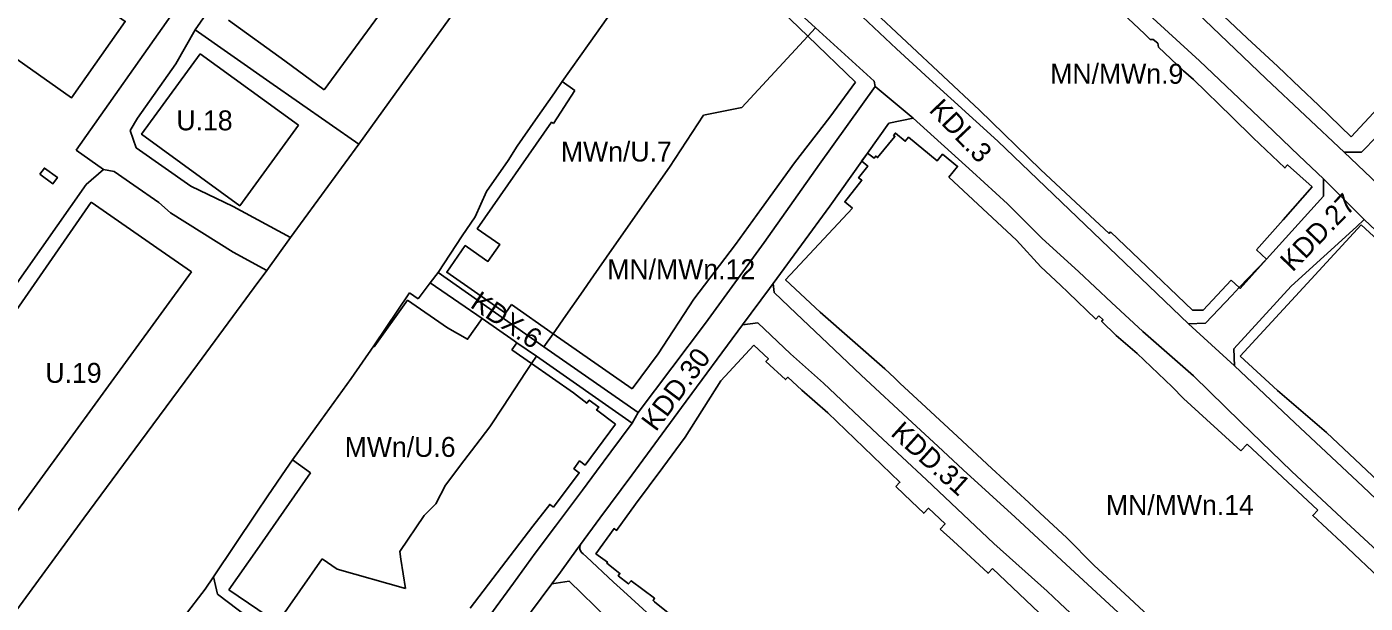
# Model space of a CAD drawing. Extents: x 7425067 to 7426806, y 5549054 to 5550619.
# Drawn here: x 7426205.4 to 7426541.6, y 5549482.5 to 5549627.2 of the extents above; entities that cross this region are included whole.
import ezdxf

# ---------------------------------------------------------------- set-up
doc = ezdxf.new("R2010")
doc.units = 0
for name, color, linetype in [('LIN_Linia Zabudowy Nieprzekraczalna', 7, 'Continuous'), ('LIN_linia zabudowy obowiązująca', 7, 'Continuous'), ('LIN_linie_rozgraniczajace', 7, 'Continuous'), ('TXT_Oznaczenia_przeznaczen', 7, 'Continuous')]:
    doc.layers.add(name, color=color, linetype=linetype)

msp = doc.modelspace()

# ---------------------------------------------------------------- linework, layer by layer
at = {"layer": 'LIN_Linia Zabudowy Nieprzekraczalna'}
for points in [[(7426538.0268, 5549599.6257), (7426544.74, 5549606.81), (7426559.36, 5549622.35), (7426563.29, 5549626.51), (7426564.58, 5549625.28), (7426566.52, 5549627.33), (7426565.24, 5549628.54), (7426567.25, 5549630.67), (7426561.59, 5549636.03), (7426548.12, 5549648.56), (7426531.28, 5549664.88), (7426518.913, 5549676.7566), (7426478.07, 5549715.98), (7426464.99, 5549727.97), (7426453.6444, 5549738.2083), (7426440.2683, 5549750.2788)], [(7426442.66, 5549689.14), (7426443.3845, 5549689.9043), (7426445.3474, 5549688.063), (7426453.04, 5549680.77), (7426454.4822, 5549679.4051), (7426458.9674, 5549675.0954), (7426463.0302, 5549671.2622), (7426469.4399, 5549665.1439), (7426475.3736, 5549659.3903), (7426481.0322, 5549653.9703), (7426484.8352, 5549650.3881), (7426488.7822, 5549646.5623), (7426492.7561, 5549642.6881), (7426498.8215, 5549636.8419), (7426511.9317, 5549624.3494), (7426519.6144, 5549617.2769), (7426525.2257, 5549611.917), (7426529.8193, 5549607.5641), (7426538.0268, 5549599.6257)], [(7426487.6123, 5549624.0024), (7426486.1182, 5549625.4194), (7426475.0591, 5549635.938), (7426467.2851, 5549643.3718), (7426463.1098, 5549647.3578), (7426452.6961, 5549657.1819), (7426444.552, 5549664.9118), (7426440.8931, 5549668.0124), (7426429.2534, 5549678.9537), (7426426.5198, 5549681.588)], [(7426378.39, 5549669.82), (7426383.61, 5549664.48), (7426386.01, 5549661.89), (7426400.55, 5549647.58), (7426399.82, 5549646.84), (7426408.17, 5549638.76), (7426409.02, 5549639.64), (7426417.3229, 5549631.8468), (7426444.72, 5549606.26), (7426460.04, 5549591.38), (7426467.6303, 5549584.2897), (7426477.25, 5549575.34), (7426477.5977, 5549575.714)], [(7426413.6, 5549613.31), (7426401.6206, 5549624.8545), (7426380, 5549645.69), (7426370.03, 5549652.54)], [(7426357.542, 5549634.3437), (7426355.61, 5549635.73), (7426346.69, 5549623.04), (7426339.9401, 5549613.4599)], [(7426256.0787, 5549628.8601), (7426270.22, 5549618.64), (7426280.1535, 5549611.3656)], [(7426489.6382, 5549622.0813), (7426489.47, 5549623.1), (7426488.36, 5549624.01), (7426487.6123, 5549624.0024)], [(7426528.27, 5549587.03), (7426522.08, 5549592.52), (7426521.4267, 5549591.7827), (7426513.4053, 5549599.3408), (7426508.0428, 5549604.5824), (7426498.4858, 5549613.9524), (7426495.9139, 5549616.1301), (7426489.6382, 5549622.0813)], [(7426339.9401, 5549613.4599), (7426343.1003, 5549611.2344)], [(7426398.29, 5549593.06), (7426407.14, 5549604.52), (7426413.6, 5549613.31)], [(7426343.1003, 5549611.2344), (7426337.727, 5549602.9229)], [(7426337.727, 5549602.9229), (7426337.26, 5549603.25), (7426318.57, 5549576.53), (7426324.24, 5549572.58), (7426321.26, 5549568.32), (7426316.12, 5549571.9), (7426315.55, 5549572.3), (7426310.91, 5549565.61), (7426325.65, 5549555.29), (7426327.1969, 5549557.4998)], [(7426437.001, 5549589.4907), (7426439.19, 5549592.16), (7426435.44, 5549595.23), (7426434.1, 5549593.59), (7426426.91, 5549599.48), (7426426.08, 5549598.48), (7426423.59, 5549600.53), (7426423.12, 5549599.95), (7426423.45, 5549599.68), (7426419.1, 5549594.37), (7426418.64, 5549594.74), (7426418.24, 5549594.21), (7426416.62, 5549595.5), (7426416.4114, 5549595.2369), (7426415.05, 5549593.52), (7426415.1399, 5549593.4485), (7426416.66, 5549592.24), (7426414.35, 5549589.33), (7426415.19, 5549588.67), (7426410.86, 5549583.24), (7426412.8563, 5549581.6544)], [(7426208.7375, 5549590.1894), (7426212.01, 5549587.83), (7426213.14, 5549589.4), (7426209.8667, 5549591.7583), (7426208.7375, 5549590.1894)], [(7426357.4565, 5549536.3315), (7426363.97, 5549545.12), (7426373, 5549558.85), (7426383.43, 5549572.57), (7426389.96, 5549581.63), (7426398.29, 5549593.06)], [(7426454, 5549573.65), (7426437.001, 5549589.4907)], [(7426514.2675, 5549571.2269), (7426520.96, 5549578.78), (7426528.27, 5549587.03)], [(7426412.8563, 5549581.6544), (7426396.03, 5549563.69), (7426404.67, 5549555.61), (7426420.91, 5549541.33), (7426423.35, 5549539.08), (7426424.73, 5549537.74), (7426431.3126, 5549531.6576), (7426439.18, 5549524.38), (7426447.81, 5549516.35), (7426457.06, 5549507.81), (7426459.86, 5549505.23), (7426466.65, 5549498.95), (7426473.46, 5549492.05), (7426482.4, 5549483.78), (7426487.2, 5549479.22), (7426492.88, 5549473.96), (7426510.35, 5549457.84), (7426515.95, 5549452.58), (7426520.98, 5549447.85), (7426523.82, 5549444.93), (7426531.3, 5549437.91), (7426537.37, 5549444.38), (7426550.43, 5549458.71), (7426562.87, 5549471.53)], [(7426477.5977, 5549575.714), (7426484.88, 5549568.76), (7426498.19, 5549556.05)], [(7426540.53, 5549577.51), (7426528.01, 5549563.88), (7426510.21, 5549544.55)], [(7426606.1385, 5549514.944), (7426600.47, 5549519.88), (7426593.35, 5549526.08), (7426546.9922, 5549567.8692), (7426548.84, 5549569.88), (7426540.53, 5549577.51)], [(7426460.12, 5549566.97), (7426454, 5549573.65)], [(7426507.94, 5549563.63), (7426509.953, 5549561.7343), (7426510.17, 5549561.53), (7426516.77, 5549568.9), (7426514.2675, 5549571.2269)], [(7426474.72, 5549554.68), (7426473.9139, 5549553.8538), (7426466.99, 5549560.48), (7426465.09, 5549562.35), (7426460.12, 5549566.97)], [(7426498.19, 5549556.05), (7426500.88, 5549556.1), (7426507.94, 5549563.63)], [(7426311.08, 5549551.63), (7426301.07, 5549558.56), (7426292.89, 5549547.1), (7426292.8, 5549546.9501), (7426292.57, 5549547.11), (7426286.93, 5549538.92), (7426279.32, 5549528.36), (7426272.2108, 5549518.4955)], [(7426327.1969, 5549557.4998), (7426337.6156, 5549550.1757), (7426357.4565, 5549536.3315)], [(7426319.7682, 5549553.9465), (7426316.13, 5549548.79), (7426311.08, 5549551.63)], [(7426327.2291, 5549546.1391), (7426328.5027, 5549547.9161), (7426327.86, 5549548.36), (7426319.7682, 5549553.9465)], [(7426493.06, 5549536.85), (7426484.31, 5549545.18), (7426479.07, 5549549.7), (7426475.36, 5549553.3), (7426475.74, 5549553.69), (7426474.72, 5549554.68)], [(7426353.3, 5549527.48), (7426348.53, 5549531.02), (7426349.07, 5549531.74), (7426346.69, 5549533.51), (7426346.09, 5549532.71), (7426342.71, 5549535.35), (7426332.2044, 5549542.6717), (7426327.2291, 5549546.1391)], [(7426388.01, 5549547.25), (7426379.73, 5549538.35), (7426370.82, 5549524.17), (7426365.2, 5549516.56), (7426358.3, 5549507.38), (7426353.55, 5549500.8), (7426352.92, 5549501.26), (7426348.36, 5549494.93), (7426351.28, 5549492.83), (7426351.09, 5549492.57), (7426354.41, 5549490), (7426353.97, 5549489.41), (7426356.55, 5549487.37), (7426357.22, 5549488.15), (7426363.12, 5549483.75), (7426362.74, 5549483.17), (7426363.13, 5549482.88), (7426378.18, 5549470.72), (7426382.81, 5549466.07), (7426382.87, 5549466.2), (7426388.4, 5549460.7), (7426394.14, 5549454.53), (7426399.56, 5549448.92), (7426403.0973, 5549445.2587)], [(7426406.59, 5549530.28), (7426400.09, 5549536.03), (7426396.58, 5549539.25), (7426396.03, 5549538.65), (7426391.08, 5549543.19), (7426391.7, 5549543.87), (7426388.01, 5549547.25)], [(7426510.21, 5549544.55), (7426519.55, 5549535.9), (7426531.82, 5549525.34), (7426540.51, 5549517.25), (7426563.54, 5549495.57), (7426577.1, 5549483.08), (7426582.613, 5549489.0782), (7426585.65, 5549486.27), (7426593.11, 5549494.36)], [(7426510.3065, 5549520.7445), (7426495.91, 5549533.91), (7426493.06, 5549536.85)], [(7426423.6718, 5549511.7983), (7426424.71, 5549512.88), (7426406.59, 5549530.28)], [(7426337.76, 5549506.6), (7426344.2, 5549515.26), (7426342.84, 5549516.27), (7426344.2897, 5549518.2197), (7426345.67, 5549517.19), (7426353.3, 5549527.48)], [(7426511.9, 5549522.46), (7426510.3065, 5549520.7445)], [(7426529.67, 5549505.9), (7426511.9, 5549522.46)], [(7426272.2108, 5549518.4955), (7426276.7026, 5549515.2122)], [(7426276.7026, 5549515.2122), (7426263.27, 5549496.01), (7426256.1733, 5549485.865)], [(7426434.84, 5549501.14), (7426436.08, 5549502.46), (7426431.9, 5549506.33), (7426430.71, 5549505.08), (7426427.63, 5549508.02), (7426423.6718, 5549511.7983)], [(7426316.82, 5549481.26), (7426332.57, 5549501.84), (7426336.7731, 5549507.332), (7426337.76, 5549506.6)], [(7426546.56, 5549487.47), (7426535.59, 5549497.8), (7426528.39, 5549504.53), (7426529.67, 5549505.9)], [(7426448, 5549491.22), (7426446.88, 5549490.04), (7426438.1, 5549498.14), (7426434.84, 5549501.14)], [(7426463.77, 5549477.75), (7426463.02, 5549476.94), (7426454.68, 5549484.87), (7426448, 5549491.22)], [(7426256.1733, 5549485.865), (7426268.433, 5549477.5449), (7426274.57, 5549473.38), (7426283.19, 5549467.53), (7426283.6963, 5549468.2744)]]:
    msp.add_lwpolyline(points, dxfattribs=at)
at = {"layer": 'LIN_linia zabudowy obowiązująca'}
for points in [[(7426203.81, 5549647.1), (7426184.83, 5549631.79), (7426216.68, 5549609.4), (7426230.16, 5549628.58), (7426203.81, 5549647.1)], [(7426280.1535, 5549611.3656), (7426296.7731, 5549634.1389)], [(7426249.01, 5549620.45), (7426234.27, 5549600.25), (7426258.92, 5549582.27), (7426273.7219, 5549602.5527)], [(7426273.7219, 5549602.5527), (7426249.01, 5549620.45)], [(7426221.62, 5549583.21), (7426169.3369, 5549507.8784)], [(7426246.8404, 5549565.7177), (7426239.21, 5549571.01), (7426221.62, 5549583.21)], [(7426192.6914, 5549491.5189), (7426246.8404, 5549565.7177)]]:
    msp.add_lwpolyline(points, dxfattribs=at)
at = {"layer": 'LIN_linie_rozgraniczajace'}
for points in [[(7426472.2007, 5549656.8053), (7426516.68, 5549614.14)], [(7426323.635, 5549645.995), (7426300.92, 5549614.51)], [(7426247.76, 5549626.42), (7426254.995, 5549637.01)], [(7426346.69, 5549623.04), (7426355.61, 5549635.73)], [(7426397, 5549632.91), (7426403.56, 5549626.95)], [(7426499.92, 5549618.67), (7426483.42, 5549633.83)], [(7426242, 5549630.59), (7426217.83, 5549596.2)], [(7426415.31, 5549629.69), (7426423.85, 5549621.67)], [(7426247.76, 5549626.42), (7426242.85, 5549617.9)], [(7426247.76, 5549626.42), (7426266.52, 5549613.31)], [(7426385.05, 5549606.95), (7426401.6206, 5549624.8545), (7426403.56, 5549626.95)], [(7426403.56, 5549626.95), (7426418.2677, 5549613.5875)], [(7426339.9401, 5549613.4599), (7426346.69, 5549623.04)], [(7426423.85, 5549621.67), (7426432.04, 5549614.18)], [(7426516.62, 5549602.85), (7426499.92, 5549618.67)], [(7426233.29, 5549604.29), (7426242.85, 5549617.9)], [(7426266.52, 5549613.31), (7426288.82, 5549597.74)], [(7426300.92, 5549614.51), (7426288.82, 5549597.74)], [(7426337.94, 5549610.62), (7426339.9401, 5549613.4599)], [(7426418.52, 5549612.2), (7426404.52, 5549592.73)], [(7426418.2677, 5549613.5875), (7426418.52, 5549612.2)], [(7426418.52, 5549612.2), (7426428.02, 5549604.31)], [(7426432.04, 5549614.18), (7426449.33, 5549598.49)], [(7426516.68, 5549614.14), (7426536.2854, 5549595.7734)], [(7426333.235, 5549603.855), (7426337.94, 5549610.62)], [(7426540.67, 5549595.7725), (7426556.37, 5549611.79)], [(7426375.36, 5549605.03), (7426385.05, 5549606.95)], [(7426231.38, 5549601.16), (7426233.29, 5549604.29)], [(7426328.6285, 5549597.2471), (7426333.235, 5549603.855)], [(7426366.8182, 5549591.9749), (7426375.36, 5549605.03)], [(7426416.57, 5549595.46), (7426421.96, 5549603.04)], [(7426421.96, 5549603.04), (7426428.02, 5549604.31)], [(7426428.02, 5549604.31), (7426442.92, 5549590.78)], [(7426524.92, 5549594.94), (7426516.62, 5549602.85)], [(7426231.38, 5549601.16), (7426232.94, 5549596.84)], [(7426449.33, 5549598.49), (7426497.2024, 5549552.684)], [(7426217.83, 5549596.2), (7426224.69, 5549591.38)], [(7426232.94, 5549596.84), (7426246.62, 5549587.22)], [(7426288.82, 5549597.74), (7426271.7, 5549574.3)], [(7426326.38, 5549593.66), (7426328.6285, 5549597.2471)], [(7426407.15, 5549582.21), (7426415.1399, 5549593.4485), (7426416.4114, 5549595.2369), (7426416.57, 5549595.46)], [(7426548.1702, 5549584.4192), (7426536.2854, 5549595.7734)], [(7426536.2854, 5549595.7734), (7426540.67, 5549595.7725)], [(7426320.92, 5549585.84), (7426326.38, 5549593.66)], [(7426352.41, 5549571.27), (7426366.8182, 5549591.9749)], [(7426404.52, 5549592.73), (7426390.61, 5549573.06)], [(7426531.1317, 5549589.012), (7426524.92, 5549594.94)], [(7426224.69, 5549591.38), (7426220.38, 5549587.66)], [(7426227.35, 5549590.86), (7426224.69, 5549591.38)], [(7426232.35, 5549587.45), (7426227.35, 5549590.86)], [(7426442.92, 5549590.78), (7426451.7, 5549582.74)], [(7426531.1317, 5549589.012), (7426541.33, 5549578.84)], [(7426531.1385, 5549584.6905), (7426531.1317, 5549589.012)], [(7426220.38, 5549587.66), (7426163.57, 5549506.84)], [(7426238.61, 5549583.09), (7426232.35, 5549587.45)], [(7426246.62, 5549587.22), (7426257.29, 5549582.08)], [(7426318.05, 5549579.51), (7426320.92, 5549585.84)], [(7426241.54, 5549580.52), (7426238.61, 5549583.09)], [(7426257.29, 5549582.08), (7426271.7, 5549574.3)], [(7426392.9036, 5549562.76), (7426407.15, 5549582.21)], [(7426451.7, 5549582.74), (7426460.38, 5549574.11)], [(7426516.77, 5549568.9), (7426531.1385, 5549584.6905)], [(7426257.28, 5549570.63), (7426241.54, 5549580.52)], [(7426314.76, 5549574.73), (7426318.05, 5549579.51)], [(7426539.3546, 5549577.0327), (7426541.33, 5549578.84)], [(7426557.16, 5549563.9), (7426541.33, 5549578.84)], [(7426523, 5549562.07), (7426539.3546, 5549577.0327)], [(7426271.7, 5549574.3), (7426265.72, 5549566.07)], [(7426308.79, 5549565.55), (7426314.76, 5549574.73)], [(7426390.61, 5549573.06), (7426375.89, 5549552.8)], [(7426460.38, 5549574.11), (7426469.69, 5549565.7)], [(7426265.72, 5549566.07), (7426257.28, 5549570.63)], [(7426347.8, 5549564.69), (7426352.41, 5549571.27)], [(7426516.77, 5549568.9), (7426509.953, 5549561.7343), (7426508.07, 5549559.755)], [(7426265.72, 5549566.07), (7426262.59, 5549561.8)], [(7426303.7345, 5549558.93), (7426306.7777, 5549562.915), (7426308.79, 5549565.55)], [(7426335.32, 5549546.9), (7426308.79, 5549565.55)], [(7426469.69, 5549565.7), (7426473.8, 5549561.86)], [(7426262.59, 5549561.8), (7426248.29, 5549542.455)], [(7426327.86, 5549548.36), (7426319.7682, 5549553.9465), (7426306.7777, 5549562.915)], [(7426344.56, 5549560.09), (7426347.8, 5549564.69)], [(7426392.01, 5549561.54), (7426385.21, 5549552.41)], [(7426392.01, 5549561.54), (7426392.9036, 5549562.76)], [(7426393.1066, 5549560.4987), (7426392.9036, 5549562.76)], [(7426473.8, 5549561.86), (7426477.9, 5549557.96)], [(7426508.5633, 5549546.4061), (7426523, 5549562.07)], [(7426292.57, 5549547.11), (7426301.54, 5549560.41)], [(7426301.54, 5549560.41), (7426303.7345, 5549558.93)], [(7426340.83, 5549554.76), (7426344.56, 5549560.09)], [(7426398.66, 5549555.225), (7426393.1066, 5549560.4987)], [(7426501.4378, 5549552.7836), (7426508.07, 5549559.755)], [(7426335.32, 5549546.9), (7426337.6156, 5549550.1757), (7426340.83, 5549554.76)], [(7426404.97, 5549549.26), (7426398.66, 5549555.225)], [(7426477.9, 5549557.96), (7426485.76, 5549550.68)], [(7426375.89, 5549552.8), (7426359.01, 5549530.37)], [(7426385.21, 5549552.41), (7426369.84, 5549531.68)], [(7426385.21, 5549552.41), (7426389.01, 5549552.89)], [(7426389.01, 5549552.89), (7426397.27, 5549545.14)], [(7426497.2024, 5549552.684), (7426501.4378, 5549552.7836)], [(7426508.7103, 5549542.139), (7426497.2024, 5549552.684)], [(7426333.42, 5549544.52), (7426328.5027, 5549547.9161), (7426327.86, 5549548.36)], [(7426415.03, 5549539.77), (7426404.97, 5549549.26)], [(7426485.76, 5549550.68), (7426498.44, 5549539.59)], [(7426286.93, 5549538.92), (7426292.57, 5549547.11)], [(7426359.01, 5549530.37), (7426335.32, 5549546.9)], [(7426397.27, 5549545.14), (7426405.53, 5549537.73)], [(7426508.7103, 5549542.139), (7426508.5633, 5549546.4061)], [(7426248.29, 5549542.455), (7426233.99, 5549523.11)], [(7426330.73, 5549540.43), (7426332.2044, 5549542.6717), (7426333.42, 5549544.52)], [(7426357.49, 5549527.71), (7426333.42, 5549544.52)], [(7426523.9, 5549527.78), (7426508.7103, 5549542.139)], [(7426279.32, 5549528.36), (7426286.93, 5549538.92)], [(7426325.16, 5549532), (7426330.73, 5549540.43)], [(7426427.83, 5549527.89), (7426415.03, 5549539.77)], [(7426498.44, 5549539.59), (7426510.35, 5549527.94)], [(7426405.53, 5549537.73), (7426419.17, 5549524.84)], [(7426321.76, 5549526.83), (7426325.16, 5549532)], [(7426369.84, 5549531.68), (7426357.42, 5549514.65)], [(7426270.47, 5549516.08), (7426272.2108, 5549518.4955), (7426279.32, 5549528.36)], [(7426359.01, 5549530.37), (7426357.49, 5549527.71)], [(7426434.215, 5549521.94), (7426427.83, 5549527.89)], [(7426510.35, 5549527.94), (7426523.1, 5549515.67)], [(7426318.23, 5549522.21), (7426321.76, 5549526.83)], [(7426357.49, 5549527.71), (7426352.12, 5549520.48)], [(7426419.17, 5549524.84), (7426431.36, 5549513.45)], [(7426541, 5549511.78), (7426523.9, 5549527.78)], [(7426233.99, 5549523.11), (7426226.87, 5549513.475)], [(7426315.2, 5549518.25), (7426318.23, 5549522.21)], [(7426440.6, 5549515.99), (7426434.215, 5549521.94)], [(7426310.62, 5549512.14), (7426315.2, 5549518.25)], [(7426352.12, 5549520.48), (7426348.54, 5549515.66)], [(7426265.98, 5549509.46), (7426270.47, 5549516.08)], [(7426348.54, 5549515.66), (7426344.97, 5549510.85)], [(7426357.42, 5549514.65), (7426349.38, 5549503.82)], [(7426453.65, 5549504.14), (7426440.6, 5549515.99)], [(7426523.1, 5549515.67), (7426535.73, 5549503.88)], [(7426226.87, 5549513.475), (7426219.75, 5549503.84)], [(7426308.2, 5549507.42), (7426310.62, 5549512.14)], [(7426431.36, 5549513.45), (7426448.35, 5549497.52)], [(7426549.35, 5549503.89), (7426541, 5549511.78)], [(7426263.03, 5549505.11), (7426265.98, 5549509.46)], [(7426344.97, 5549510.85), (7426338.26, 5549501.82)], [(7426250.22, 5549486.01), (7426252.3345, 5549489.1627), (7426263.03, 5549505.11)], [(7426299.1, 5549495.52), (7426305.25, 5549504.53)], [(7426305.25, 5549504.53), (7426308.2, 5549507.42)], [(7426219.75, 5549503.84), (7426202.0428, 5549479.5722), (7426192.8, 5549466.905)], [(7426338.26, 5549501.82), (7426333.13, 5549495.07)], [(7426349.38, 5549503.82), (7426344.526, 5549497.2558), (7426343.76, 5549496.22)], [(7426466.45, 5549492.21), (7426453.65, 5549504.14)], [(7426535.73, 5549503.88), (7426544.575, 5549495.645)], [(7426299.35, 5549493.54), (7426299.1, 5549495.52)], [(7426333.13, 5549495.07), (7426327.68, 5549487.52)], [(7426343.76, 5549496.22), (7426339.46, 5549490.27)], [(7426344.31, 5549496.73), (7426344.526, 5549497.2558)], [(7426344.36, 5549496.07), (7426344.31, 5549496.73)], [(7426344.7, 5549495.36), (7426344.36, 5549496.07)], [(7426345.19, 5549494.94), (7426344.7, 5549495.36)], [(7426346.05, 5549494.14), (7426345.19, 5549494.94)], [(7426448.35, 5549497.52), (7426461.69, 5549485.52)], [(7426266.52, 5549474.7853), (7426268.433, 5549477.5449), (7426279.59, 5549493.64)], [(7426279.59, 5549493.64), (7426283.36, 5549491.03)], [(7426283.36, 5549491.03), (7426300.57, 5549486.23)], [(7426300.57, 5549486.23), (7426299.35, 5549493.54)], [(7426352.8, 5549487.82), (7426346.05, 5549494.14)], [(7426479.49, 5549480.23), (7426466.45, 5549492.21)], [(7426252.3345, 5549489.1627), (7426253.35, 5549484.75)], [(7426327.68, 5549487.52), (7426318.3, 5549474.76)], [(7426339.46, 5549490.27), (7426337.31, 5549487.4)], [(7426337.31, 5549487.4), (7426341.6185, 5549488.0696)], [(7426341.6185, 5549488.0696), (7426351.279, 5549478.7147)], [(7426355.28, 5549485.53), (7426352.8, 5549487.82)], [(7426244.99, 5549479.2), (7426250.22, 5549486.01)], [(7426253.35, 5549484.75), (7426266.52, 5549474.7853)], [(7426337.31, 5549487.4), (7426326.8, 5549473.28)], [(7426365.92, 5549475.81), (7426355.28, 5549485.53)], [(7426461.69, 5549485.52), (7426464.9, 5549482.54)], [(7426464.9, 5549482.54), (7426469.99, 5549477.79)]]:
    msp.add_lwpolyline(points, dxfattribs=at)

# ---------------------------------------------------------------- texts
at = {"layer": 'TXT_Oznaczenia_przeznaczen'}
for s, p in [('MN/MWn.9', (7426462.4641, 5549612.9144)), ('U.18', (7426243.0122, 5549601.2176)), ('MWn/U.7', (7426339.5724, 5549593.3912)), ('MN/MWn.12', (7426351.2226, 5549563.844)), ('U.19', (7426210.1051, 5549537.8319)), ('MWn/U.6', (7426285.2736, 5549519.2445)), ('MN/MWn.14', (7426476.46, 5549504.6481))]:
    msp.add_text(s, height=5, dxfattribs=at).set_placement(p)
for s, rotation, p in [('KDL.3', 313.57189, (7426431.8117, 5549606.1355)), ('KDD.27', 46.068083, (7426523.3569, 5549565.4717)), ('KDX.6', 325.929925, (7426316.542, 5549556.9723)), ('KDD.30', 53.307227, (7426363.4418, 5549525.3797)), ('KDD.31', 317.907951, (7426422.1556, 5549524.8316))]:
    msp.add_text(s, height=5, rotation=rotation, dxfattribs=at).set_placement(p)

doc.saveas('drawing.dxf')
